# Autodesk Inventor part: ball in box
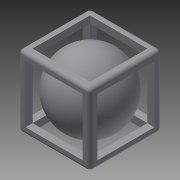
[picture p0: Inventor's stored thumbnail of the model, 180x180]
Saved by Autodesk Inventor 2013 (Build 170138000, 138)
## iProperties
Created: 2013-04
Part Number: ball in box
Material: Generic
Document SubType Name: Modeling
Designer: parmelee.scott
Density: 1 g/cm^3
Author: parmelee.scott
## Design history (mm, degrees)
sketch "Sketch1"
  geometry: L1 (-5.324, 9.394)-(20.076, 9.394); L2 (20.076, 9.394)-(20.076, -16.006); L3 (20.076, -16.006)-(-5.324, -16.006); L4 (-5.324, -16.006)-(-5.324, 9.394); L5 (17.536, 6.854)-(-2.784, 6.854); L6 (-2.784, 6.854)-(-2.784, -13.466); L7 (-2.784, -13.466)-(17.536, -13.466); L8 (17.536, -13.466)-(17.536, 6.854); 1 further point
  constraints: 16 end point, 4 parallel, 2 perpendicular, 1 horizontal, 3 other
  dimensions: "d0" = 25.4 distance of L2.end L3.end; "d1" = 25.4 distance of L1.end L2.end; "d2" = 2.54 distance between parallel lines of L1 L5
extrude "Extrusion1" new body sketch "Sketch1" distance "d3" = 25.4; taper "d4" = 0 deg
sketch "Sketch2"
  geometry: L1 (25.4, 0)-(0, 0) reference; L2 (25.4, 0)-(25.4, 25.4) reference; L3 (0, 25.4)-(25.4, 25.4) reference; L4 (0, 0)-(0, 25.4) reference; L5 (22.86, 22.86)-(22.86, 2.54); L6 (22.86, 2.54)-(2.54, 2.54); L7 (2.54, 2.54)-(2.54, 22.86); L8 (2.54, 22.86)-(22.86, 22.86); 1 further point
  constraints: 8 end point, 3 other
  dimensions: "d6" = 2.54 distance between parallel lines of L8 L3
extrude "Extrusion2" cut sketch "Sketch2" distance "d7" = 25.4; taper "d8" = 0 deg
sketch "Sketch3"
  geometry: L1 (25.4, 0)-(0, 0) reference; L2 (25.4, 0)-(25.4, 25.4) reference; L3 (0, 25.4)-(25.4, 25.4) reference; L4 (0, 0)-(0, 25.4) reference; L5 (22.86, 22.86)-(22.86, 2.54); L6 (22.86, 2.54)-(2.54, 2.54); L7 (2.54, 2.54)-(2.54, 22.86); L8 (2.54, 22.86)-(22.86, 22.86); 1 further point
  constraints: 8 end point, 3 other
  dimensions: "d9" = 2.54 distance between parallel lines of L3 L8
extrude "Extrusion3" cut sketch "Sketch3" distance "d10" = 25.4; taper "d11" = 0 deg
workplane "Work Plane1"
sketch "Sketch4"
  geometry: L1 (2.54, 22.86)-(22.86, 22.86) reference; L2 (22.86, 22.86)-(22.86, 2.54) reference; L3 (22.86, 2.54)-(2.54, 2.54) reference; L4 (2.54, 2.54)-(2.54, 22.86) reference; L5 (25.4, 0)-(0, 0) reference; L6 (25.4, 0)-(25.4, 25.4) reference; L7 (0, 25.4)-(25.4, 25.4) reference; L8 (0, 0)-(0, 25.4) reference; L9 (12.7, 25.4)-(12.7, 0); A1 r 12.7 centre (12.7, 12.7) between (12.7, 25.4) and (12.7, 0); 1 further point
  constraints: 2 end point, 2 midpoint, 2 point on circle, 1 centre point, 1 tangent
revolve "Revolution1" sketch "Sketch4" stored, may be unused: angle "d12" = 90 deg
fillet "Fillet1" dims "d13" = 1.27
body "Solid1"
node "Projected Loop1"
